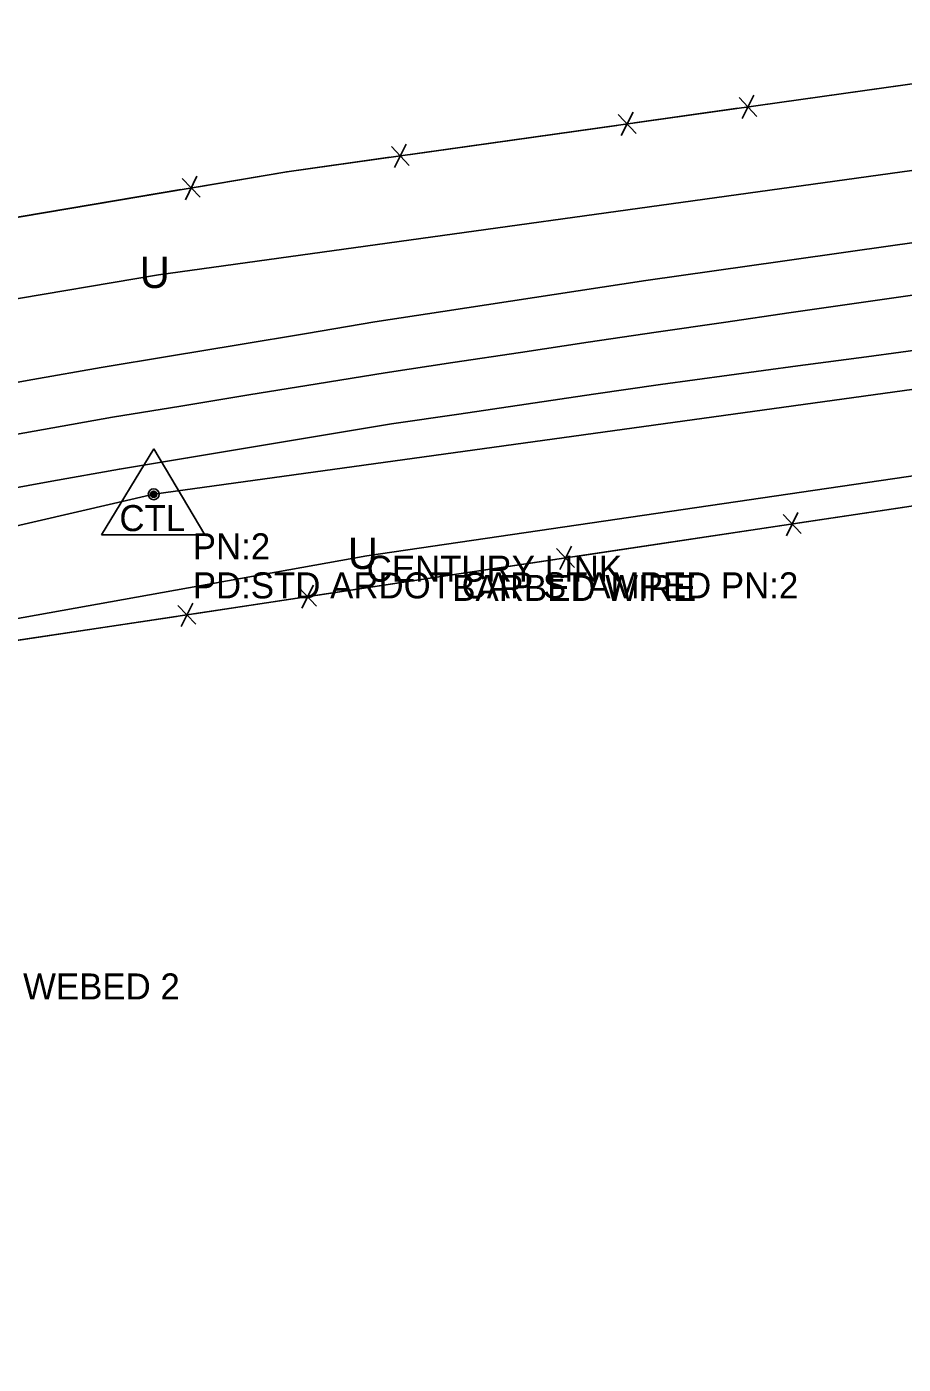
# Model space of a CAD drawing. Extents: x 1568433 to 1572450, y 731863 to 733450.
# Drawn here: x 1569814.5 to 1569982.8, y 731973.5 to 732230.5 of the extents above; entities that cross this region are included whole.
import ezdxf

# ---------------------------------------------------------------- set-up
doc = ezdxf.new("R2010")
doc.units = 0
for name, color, linetype in [('Default', 7, 'Continuous'), ('S_BASELINE', 7, 'Continuous'), ('S_EDGE_PAVEMENT', 7, 'Continuous'), ('S_FENCE', 7, 'Continuous'), ('S_FENCE_ANNOT', 7, 'Continuous'), ('S_MSC_PT_SYM', 7, 'Continuous'), ('S_PAVEMENT_CROWN', 7, 'Continuous'), ('S_PRIMARY_CTL', 7, 'Continuous'), ('S_PRIMARY_CTL_ANNOT', 7, 'Continuous'), ('S_UNDERGROUND_CABLE', 7, 'Continuous'), ('S_UNDERGROUND_CABLE_ANNOT', 7, 'Continuous')]:
    doc.layers.add(name, color=color, linetype=linetype)

msp = doc.modelspace()

# ---------------------------------------------------------------- linework, layer by layer
at = {"layer": 'Default'}
for points in [[(1569838.84, 732140.65), (1569838.84, 732140.7), (1569838.84, 732140.65), (1569838.79, 732140.65), (1569838.84, 732140.65), (1569838.84, 732140.6), (1569838.84, 732140.65), (1569838.89, 732140.65)], [(1569838.86, 732140.64), (1569838.86, 732140.69), (1569838.86, 732140.64), (1569838.81, 732140.64), (1569838.86, 732140.64), (1569838.86, 732140.59), (1569838.86, 732140.64), (1569838.91, 732140.64)]]:
    msp.add_lwpolyline(points, dxfattribs=at)
at = {"layer": 'S_BASELINE'}
for p, q in [((1569838.9, 732140.65), (1570488.07, 732230.45)), ((1569114.63, 731973.54), (1569838.9, 732140.65))]:
    msp.add_line(p, q, dxfattribs=at)
at = {"layer": 'S_EDGE_PAVEMENT'}
for points in [[(1569802.59, 732160.35), (1569815.71, 732162.68), (1569828.83, 732165.01), (1569841.96, 732167.19), (1569855.1, 732169.38), (1569868.24, 732171.56), (1569881.38, 732173.75), (1569894.39, 732175.74), (1569907.4, 732177.73), (1569920.41, 732179.73), (1569933.42, 732181.72), (1569946.52, 732183.57), (1569959.63, 732185.42), (1569972.73, 732187.27), (1569985.84, 732189.13)], [(1569806.33, 732140.81), (1569819.33, 732143.14), (1569832.33, 732145.47), (1569845.39, 732147.64), (1569858.45, 732149.82), (1569871.51, 732151.99), (1569884.56, 732154.16), (1569897.49, 732156.06), (1569910.41, 732157.95), (1569923.33, 732159.85), (1569936.25, 732161.75), (1569949.43, 732163.52), (1569962.62, 732165.29), (1569975.8, 732167.05), (1569988.99, 732168.82)]]:
    msp.add_lwpolyline(points, dxfattribs=at)
at = {"layer": 'S_FENCE'}
for p, q in [((1569864.46, 732202.58), (1570061.14, 732230.29)), ((1569951.31, 732216.89), (1569954.72, 732213.23)), ((1569951.31, 732216.89), (1569954.72, 732213.23)), ((1569951.88, 732212.83), (1569954.15, 732217.29)), ((1569951.88, 732212.83), (1569954.15, 732217.29)), ((1569928.68, 732209.56), (1569930.95, 732214.02)), ((1569928.68, 732209.56), (1569930.95, 732214.02)), ((1569928.11, 732213.62), (1569931.52, 732209.96)), ((1569928.11, 732213.62), (1569931.52, 732209.96)), ((1569884.54, 732207.48), (1569887.95, 732203.82)), ((1569884.54, 732207.48), (1569887.95, 732203.82)), ((1569885.11, 732203.42), (1569887.38, 732207.88)), ((1569885.11, 732203.42), (1569887.38, 732207.88)), ((1569648.06, 732166.13), (1569864.46, 732202.58)), ((1569844.34, 732201.27), (1569847.85, 732197.71)), ((1569844.34, 732201.27), (1569847.85, 732197.71)), ((1569845.02, 732197.23), (1569847.17, 732201.75)), ((1569845.02, 732197.23), (1569847.17, 732201.75)), ((1569896.24, 732125.16), (1570045.5, 732147.5)), ((1569959.79, 732136.74), (1569963.23, 732133.12)), ((1569959.79, 732136.74), (1569963.23, 732133.12)), ((1569960.39, 732132.69), (1569962.62, 732137.17)), ((1569960.39, 732132.69), (1569962.62, 732137.17)), ((1569916.27, 732130.23), (1569919.72, 732126.6)), ((1569916.27, 732130.23), (1569919.72, 732126.6)), ((1569916.88, 732126.18), (1569919.11, 732130.65)), ((1569916.88, 732126.18), (1569919.11, 732130.65)), ((1569713.34, 732097.66), (1569896.24, 732125.16)), ((1569866.73, 732122.8), (1569870.18, 732119.17)), ((1569866.73, 732122.8), (1569870.18, 732119.17)), ((1569867.34, 732118.74), (1569869.57, 732123.22)), ((1569867.34, 732118.74), (1569869.57, 732123.22)), ((1569843.56, 732119.31), (1569847, 732115.69)), ((1569843.56, 732119.31), (1569847, 732115.69)), ((1569844.17, 732115.26), (1569846.39, 732119.74)), ((1569844.17, 732115.26), (1569846.39, 732119.74))]:
    msp.add_line(p, q, dxfattribs=at)
for points in [[(1569955, 732215.34), (1569994.61, 732220.92)], [(1569955, 732215.34), (1569994.61, 732220.92)], [(1569931.23, 732211.99), (1569951.04, 732214.78)], [(1569931.23, 732211.99), (1569951.04, 732214.78)], [(1569888.23, 732205.93), (1569927.83, 732211.51)], [(1569888.23, 732205.93), (1569927.83, 732211.51)], [(1569864.46, 732202.58), (1569884.27, 732205.37)], [(1569864.46, 732202.58), (1569884.27, 732205.37)], [(1569847.51, 732199.73), (1569864.46, 732202.58)], [(1569847.51, 732199.73), (1569864.46, 732202.58)], [(1569804.69, 732192.51), (1569844.12, 732199.16)], [(1569804.69, 732192.51), (1569844.12, 732199.16)], [(1569962.93, 732135.14), (1569982.71, 732138.1)], [(1569962.93, 732135.14), (1569982.71, 732138.1)], [(1569919.97, 732128.71), (1569959.53, 732134.63)], [(1569919.97, 732128.71), (1569959.53, 732134.63)], [(1569896.24, 732125.16), (1569916.02, 732128.12)], [(1569896.24, 732125.16), (1569916.02, 732128.12)], [(1569870.43, 732121.28), (1569896.24, 732125.16)], [(1569870.43, 732121.28), (1569896.24, 732125.16)], [(1569846.7, 732117.71), (1569866.48, 732120.69)], [(1569846.7, 732117.71), (1569866.48, 732120.69)], [(1569803.75, 732111.25), (1569843.3, 732117.2)], [(1569803.75, 732111.25), (1569843.3, 732117.2)]]:
    msp.add_lwpolyline(points, dxfattribs=at)
at = {"layer": 'S_MSC_PT_SYM'}
for points in [[(1569864.46, 732202.58), (1569864.46, 732202.63), (1569864.46, 732202.58), (1569864.41, 732202.58), (1569864.46, 732202.58), (1569864.46, 732202.53), (1569864.46, 732202.58), (1569864.51, 732202.58)], [(1569896.24, 732125.16), (1569896.24, 732125.21), (1569896.24, 732125.16), (1569896.19, 732125.16), (1569896.24, 732125.16), (1569896.24, 732125.11), (1569896.24, 732125.16), (1569896.29, 732125.16)]]:
    msp.add_lwpolyline(points, dxfattribs=at)
at = {"layer": 'S_PAVEMENT_CROWN'}
msp.add_lwpolyline([(1569804.41, 732150.72), (1569817.71, 732153.08), (1569831.01, 732155.45), (1569844.09, 732157.59), (1569857.18, 732159.72), (1569870.26, 732161.86), (1569883.35, 732163.99), (1569896.35, 732165.95), (1569909.36, 732167.9), (1569922.36, 732169.85), (1569935.37, 732171.8), (1569948.34, 732173.67), (1569961.32, 732175.54), (1569974.3, 732177.4), (1569987.27, 732179.27)], dxfattribs=at)
at = {"layer": 'S_PRIMARY_CTL'}
for p, q in [((1569838.9, 732149.35), (1569828.86, 732132.83)), ((1569838.9, 732149.35), (1569828.86, 732132.83)), ((1569838.9, 732149.35), (1569848.72, 732132.83)), ((1569838.9, 732149.35), (1569848.72, 732132.83)), ((1569828.86, 732132.83), (1569848.72, 732132.83)), ((1569828.86, 732132.83), (1569848.72, 732132.83))]:
    msp.add_line(p, q, dxfattribs=at)
for radius in [1.04, 1.04, 0.609, 0.609, 0.344, 0.344]:
    msp.add_circle((1569838.9, 732140.65), radius, dxfattribs=at)
at = {"layer": 'S_UNDERGROUND_CABLE'}
for p, q in [((1569839.84, 732182.82), (1570079.83, 732216.06)), ((1569645.93, 732150.12), (1569839.84, 732182.82)), ((1569879.8, 732128.85), (1570045.33, 732153.09)), ((1569718.51, 732099.8), (1569879.8, 732128.85))]:
    msp.add_line(p, q, dxfattribs=at)

# ---------------------------------------------------------------- texts
at = {"layer": 'Default'}
for p in [(1569836.21, 732180.27), (1569876.17, 732126.3)]:
    msp.add_text('U', height=6, dxfattribs=at).set_placement(p)
at = {"layer": 'S_FENCE_ANNOT'}
for s, p in [('BARBED WIRE', (1569896.24, 732120.16)), ('8FT WEBED 2 BARBED 3FT WEBED 2 ', (1569725.02, 732043.61))]:
    msp.add_text(s, height=5, dxfattribs=at).set_placement(p)
at = {"layer": 'S_PRIMARY_CTL'}
msp.add_text('CTL', height=5, rotation=360, dxfattribs=at).set_placement((1569832.31, 732133.57))
msp.add_text('CTL', height=5, dxfattribs=at).set_placement((1569832.31, 732133.57))
at = {"layer": 'S_PRIMARY_CTL_ANNOT'}
for s, p in [('PN:2', (1569846.4, 732128.15)), ('PD:STD ARDOT CAP STAMPED PN:2', (1569846.4, 732120.65))]:
    msp.add_text(s, height=5, dxfattribs=at).set_placement(p)
at = {"layer": 'S_UNDERGROUND_CABLE_ANNOT'}
msp.add_text('CENTURY LINK', height=5, dxfattribs=at).set_placement((1569879.8, 732123.85))

doc.saveas('drawing.dxf')
